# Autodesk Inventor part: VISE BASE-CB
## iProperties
Created: 2006-07
Part Number: VISE BASE-CB
Material: Cast Iron
Document SubType Name: Modeling
Designer: rollin42
Density: 7.25 g/cm^3
Stock Number: VISE BASE-CB
Author: rollin42
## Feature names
1. Extrusion1
2. Extrusion2
3. Extrusion3
4. Extrusion4
5. Fillet1
6. Fillet2
7. Fillet3
8. Extrusion5
9. Fillet4
10. Extrusion6
11. Mirror1
12. Hole1
13. Coil1
